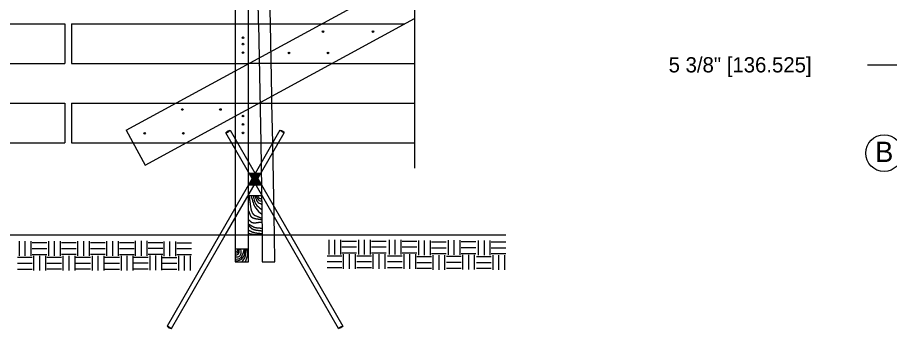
# Model space of a CAD drawing. Extents: x 49991 to 79985, y 47703 to 60542.
# Drawn here: x 50005.885 to 50009.323, y 49994.397 to 49995.622 of the extents above; entities that cross this region are included whole.
import ezdxf

# ---------------------------------------------------------------- set-up
doc = ezdxf.new("R2010")
doc.units = 0
for name, color, linetype in [('Level 1', 7, 'Continuous'), ('Level 2', 7, 'Continuous'), ('Level 3', 7, 'Continuous'), ('Level 4', 7, 'Continuous'), ('Level 6', 7, 'Continuous')]:
    doc.layers.add(name, color=color, linetype=linetype)

msp = doc.modelspace()

# ---------------------------------------------------------------- linework, layer by layer
at = {"layer": 'Level 1'}
for p, q in [((50006.3134, 49995.1775), (50007.4507, 49995.7955)), ((50006.7436, 49995.7523), (50006.7436, 49995.5963)), ((50006.7956, 49995.5963), (50006.7956, 49995.7523)), ((50006.8357, 49995.5963), (50006.8326, 49995.7523)), ((50006.8827, 49995.5963), (50006.8798, 49995.7523)), ((50005.0943, 49995.5963), (50006.0719, 49995.5963)), ((50006.0719, 49995.5963), (50006.0719, 49995.4403)), ((50006.0979, 49995.5963), (50006.0979, 49995.4403)), ((50006.0979, 49995.5963), (50007.0841, 49995.5963)), ((50006.388, 49995.0404), (50007.4507, 49995.618)), ((50005.3814, 49995.4403), (50006.0719, 49995.4403)), ((50006.0979, 49995.4403), (50006.797, 49995.4403)), ((50006.7436, 49995.4403), (50006.7436, 49995.4113)), ((50007.1237, 49995.4403), (50007.4507, 49995.4403)), ((50006.8885, 49995.2843), (50006.8879, 49995.3122)), ((50005.6684, 49995.2843), (50006.0719, 49995.2843)), ((50006.0719, 49995.2843), (50006.0719, 49995.1283)), ((50006.0979, 49995.2843), (50006.0979, 49995.1283)), ((50006.0979, 49995.2843), (50006.5099, 49995.2843)), ((50006.8367, 49995.2843), (50007.4507, 49995.2843)), ((50006.3134, 49995.1775), (50006.388, 49995.0404)), ((50006.7234, 49995.1776), (50006.8218, 49995.0072)), ((50006.9201, 49995.1775), (50006.8218, 49995.0072)), ((50006.8105, 49994.9876), (50006.7065, 49995.1678)), ((50006.833, 49994.9877), (50006.937, 49995.1678)), ((50005.7974, 49995.1283), (50006.0719, 49995.1283)), ((50006.0979, 49995.1283), (50006.3402, 49995.1283)), ((50006.5496, 49995.1283), (50007.4507, 49995.1283)), ((50006.7436, 49995.1283), (50006.7436, 49994.7643)), ((50006.7956, 49994.7643), (50006.7956, 49995.1283)), ((50006.845, 49995.1283), (50006.8495, 49994.7643)), ((50006.8985, 49994.7643), (50006.8914, 49995.1283)), ((50006.798, 49995.0092), (50006.8454, 49995.0092)), ((50006.7995, 49995.0066), (50006.8439, 49995.0066)), ((50006.801, 49995.004), (50006.8424, 49995.004)), ((50006.8025, 49995.0014), (50006.8409, 49995.0014)), ((50006.8105, 49994.9876), (50006.6815, 49994.7643)), ((50006.704, 49994.7643), (50006.8217, 49994.9682)), ((50006.7989, 49994.9676), (50006.8446, 49994.9676)), ((50006.8005, 49994.9702), (50006.8431, 49994.9702)), ((50006.802, 49994.9728), (50006.8416, 49994.9728)), ((50006.8035, 49994.9754), (50006.8401, 49994.9754)), ((50006.804, 49994.9988), (50006.8394, 49994.9988)), ((50006.805, 49994.978), (50006.8386, 49994.978)), ((50006.8055, 49994.9962), (50006.8379, 49994.9962)), ((50006.8065, 49994.9806), (50006.8371, 49994.9806)), ((50006.807, 49994.9936), (50006.8364, 49994.9936)), ((50006.808, 49994.9832), (50006.8356, 49994.9832)), ((50006.8085, 49994.991), (50006.8349, 49994.991)), ((50006.8095, 49994.9858), (50006.8341, 49994.9858)), ((50006.81, 49994.9884), (50006.8334, 49994.9884)), ((50006.9395, 49994.7643), (50006.8217, 49994.9682)), ((50006.833, 49994.9877), (50006.962, 49994.7643)), ((50006.7959, 49994.9624), (50006.8476, 49994.9624)), ((50006.7974, 49994.965), (50006.8461, 49994.965)), ((50006.8476, 49994.9194), (50006.7956, 49994.9194)), ((50006.7956, 49994.7643), (50006.7956, 49994.8423)), ((50007.8111, 49994.7643), (50000.0394, 49994.7643)), ((50005.8914, 49994.7409), (50005.8914, 49994.6831)), ((50005.9145, 49994.7409), (50005.9145, 49994.6831)), ((50005.9377, 49994.7409), (50005.9377, 49994.6831)), ((50005.943, 49994.7355), (50006.0009, 49994.7355)), ((50006.0073, 49994.7414), (50006.0073, 49994.6836)), ((50006.0304, 49994.7414), (50006.0304, 49994.6836)), ((50006.0535, 49994.7414), (50006.0535, 49994.6836)), ((50006.0589, 49994.736), (50006.1167, 49994.736)), ((50006.1219, 49994.7415), (50006.1219, 49994.6836)), ((50006.145, 49994.7415), (50006.145, 49994.6836)), ((50006.1681, 49994.7415), (50006.1681, 49994.6836)), ((50006.1735, 49994.7361), (50006.2313, 49994.7361)), ((50006.2362, 49994.7409), (50006.2362, 49994.6831)), ((50006.2593, 49994.7409), (50006.2593, 49994.6831)), ((50006.2824, 49994.7409), (50006.2824, 49994.6831)), ((50006.2878, 49994.7356), (50006.3456, 49994.7356)), ((50006.3494, 49994.742), (50006.3494, 49994.6841)), ((50006.3725, 49994.742), (50006.3725, 49994.6841)), ((50006.3956, 49994.742), (50006.3956, 49994.6841)), ((50006.401, 49994.7366), (50006.4588, 49994.7366)), ((50006.4621, 49994.7404), (50006.4621, 49994.6826)), ((50006.4852, 49994.7404), (50006.4852, 49994.6826)), ((50006.5084, 49994.7404), (50006.5084, 49994.6826)), ((50006.5137, 49994.735), (50006.5716, 49994.735)), ((50007.1124, 49994.747), (50007.1124, 49994.6892)), ((50007.1356, 49994.747), (50007.1356, 49994.6892)), ((50007.1587, 49994.747), (50007.1587, 49994.6892)), ((50007.164, 49994.7416), (50007.2219, 49994.7416)), ((50007.2294, 49994.747), (50007.2294, 49994.6892)), ((50007.2525, 49994.747), (50007.2525, 49994.6892)), ((50007.2756, 49994.747), (50007.2756, 49994.6892)), ((50007.281, 49994.7416), (50007.3388, 49994.7416)), ((50007.3504, 49994.747), (50007.3504, 49994.6892)), ((50007.3735, 49994.747), (50007.3735, 49994.6892)), ((50007.3967, 49994.747), (50007.3967, 49994.6892)), ((50007.402, 49994.7416), (50007.4599, 49994.7416)), ((50007.4658, 49994.7439), (50007.4658, 49994.686)), ((50007.4889, 49994.7439), (50007.4889, 49994.686)), ((50007.512, 49994.7439), (50007.512, 49994.686)), ((50007.5174, 49994.7385), (50007.5752, 49994.7385)), ((50007.5826, 49994.7449), (50007.5826, 49994.6871)), ((50007.6058, 49994.7449), (50007.6058, 49994.6871)), ((50007.6289, 49994.7449), (50007.6289, 49994.6871)), ((50007.6343, 49994.7395), (50007.6921, 49994.7395)), ((50007.7017, 49994.7439), (50007.7017, 49994.686)), ((50007.7248, 49994.7439), (50007.7248, 49994.686)), ((50007.7479, 49994.7439), (50007.7479, 49994.686)), ((50007.7533, 49994.7385), (50007.8111, 49994.7385)), ((50005.943, 49994.7124), (50006.0009, 49994.7124)), ((50006.0589, 49994.7129), (50006.1167, 49994.7129)), ((50006.1735, 49994.713), (50006.2313, 49994.713)), ((50006.2878, 49994.7124), (50006.3456, 49994.7124)), ((50006.401, 49994.7135), (50006.4588, 49994.7135)), ((50006.5137, 49994.7119), (50006.5716, 49994.7119)), ((50007.164, 49994.7185), (50007.2219, 49994.7185)), ((50007.164, 49994.6953), (50007.2219, 49994.6953)), ((50007.281, 49994.7185), (50007.3388, 49994.7185)), ((50007.281, 49994.6953), (50007.3388, 49994.6953)), ((50007.402, 49994.7185), (50007.4599, 49994.7185)), ((50007.402, 49994.6953), (50007.4599, 49994.6953)), ((50007.5174, 49994.7154), (50007.5752, 49994.7154)), ((50007.5174, 49994.6922), (50007.5752, 49994.6922)), ((50007.6343, 49994.7164), (50007.6921, 49994.7164)), ((50007.6343, 49994.6933), (50007.6921, 49994.6933)), ((50007.7533, 49994.7154), (50007.8111, 49994.7154)), ((50007.7533, 49994.6922), (50007.8111, 49994.6922)), ((50005.8852, 49994.6777), (50005.943, 49994.6777)), ((50005.943, 49994.6893), (50006.0009, 49994.6893)), ((50005.9488, 49994.6835), (50005.9488, 49994.6257)), ((50005.9719, 49994.6835), (50005.9719, 49994.6257)), ((50005.9951, 49994.6835), (50005.9951, 49994.6257)), ((50006.0011, 49994.6782), (50006.0589, 49994.6782)), ((50006.0589, 49994.6898), (50006.1167, 49994.6898)), ((50006.0647, 49994.684), (50006.0647, 49994.6262)), ((50006.0878, 49994.684), (50006.0878, 49994.6262)), ((50006.1109, 49994.684), (50006.1109, 49994.6262)), ((50006.1156, 49994.6782), (50006.1735, 49994.6782)), ((50006.1735, 49994.6898), (50006.2313, 49994.6898)), ((50006.1792, 49994.684), (50006.1792, 49994.6262)), ((50006.2024, 49994.684), (50006.2024, 49994.6262)), ((50006.2255, 49994.684), (50006.2255, 49994.6262)), ((50006.2299, 49994.6777), (50006.2878, 49994.6777)), ((50006.2878, 49994.6893), (50006.3456, 49994.6893)), ((50006.2935, 49994.6835), (50006.2935, 49994.6257)), ((50006.3167, 49994.6835), (50006.3167, 49994.6257)), ((50006.3398, 49994.6835), (50006.3398, 49994.6257)), ((50006.3432, 49994.6788), (50006.401, 49994.6788)), ((50006.401, 49994.6903), (50006.4588, 49994.6903)), ((50006.4068, 49994.6846), (50006.4068, 49994.6267)), ((50006.4299, 49994.6846), (50006.4299, 49994.6267)), ((50006.453, 49994.6846), (50006.453, 49994.6267)), ((50006.4559, 49994.6772), (50006.5137, 49994.6772)), ((50006.5137, 49994.6888), (50006.5716, 49994.6888)), ((50006.5195, 49994.683), (50006.5195, 49994.6252)), ((50006.5426, 49994.683), (50006.5426, 49994.6252)), ((50006.5658, 49994.683), (50006.5658, 49994.6252)), ((50007.1062, 49994.6838), (50007.164, 49994.6838)), ((50007.1062, 49994.6607), (50007.164, 49994.6607)), ((50007.1698, 49994.6896), (50007.1698, 49994.6317)), ((50007.193, 49994.6896), (50007.193, 49994.6317)), ((50007.2161, 49994.6896), (50007.2161, 49994.6317)), ((50007.2231, 49994.6838), (50007.281, 49994.6838)), ((50007.2231, 49994.6607), (50007.281, 49994.6607)), ((50007.2867, 49994.6896), (50007.2867, 49994.6317)), ((50007.3099, 49994.6896), (50007.3099, 49994.6317)), ((50007.333, 49994.6896), (50007.333, 49994.6317)), ((50007.3442, 49994.6838), (50007.402, 49994.6838)), ((50007.3442, 49994.6607), (50007.402, 49994.6607)), ((50007.4078, 49994.6896), (50007.4078, 49994.6317)), ((50007.4309, 49994.6896), (50007.4309, 49994.6317)), ((50007.4541, 49994.6896), (50007.4541, 49994.6317)), ((50007.4595, 49994.6807), (50007.5174, 49994.6807)), ((50007.4595, 49994.6575), (50007.5174, 49994.6575)), ((50007.5231, 49994.6865), (50007.5231, 49994.6286)), ((50007.5463, 49994.6865), (50007.5463, 49994.6286)), ((50007.5694, 49994.6865), (50007.5694, 49994.6286)), ((50007.5764, 49994.6817), (50007.6343, 49994.6817)), ((50007.5764, 49994.6586), (50007.6343, 49994.6586)), ((50007.64, 49994.6875), (50007.64, 49994.6297)), ((50007.6632, 49994.6875), (50007.6632, 49994.6297)), ((50007.6863, 49994.6875), (50007.6863, 49994.6297)), ((50007.6954, 49994.6807), (50007.7533, 49994.6807)), ((50007.6954, 49994.6575), (50007.7533, 49994.6575)), ((50007.759, 49994.6865), (50007.759, 49994.6286)), ((50007.7822, 49994.6865), (50007.7822, 49994.6286)), ((50007.8053, 49994.6865), (50007.8053, 49994.6286)), ((50005.8852, 49994.6546), (50005.943, 49994.6546)), ((50005.8852, 49994.6314), (50005.943, 49994.6314)), ((50006.0011, 49994.6551), (50006.0589, 49994.6551)), ((50006.0011, 49994.632), (50006.0589, 49994.632)), ((50006.1156, 49994.6551), (50006.1735, 49994.6551)), ((50006.1156, 49994.632), (50006.1735, 49994.632)), ((50006.2299, 49994.6546), (50006.2878, 49994.6546)), ((50006.2299, 49994.6315), (50006.2878, 49994.6315)), ((50006.3432, 49994.6557), (50006.401, 49994.6557)), ((50006.3432, 49994.6325), (50006.401, 49994.6325)), ((50006.4559, 49994.6541), (50006.5137, 49994.6541)), ((50006.4559, 49994.6309), (50006.5137, 49994.6309)), ((50007.1062, 49994.6375), (50007.164, 49994.6375)), ((50007.2231, 49994.6375), (50007.281, 49994.6375)), ((50007.3442, 49994.6375), (50007.402, 49994.6375)), ((50007.4595, 49994.6344), (50007.5174, 49994.6344)), ((50007.5764, 49994.6354), (50007.6343, 49994.6354)), ((50007.6954, 49994.6344), (50007.7533, 49994.6344))]:
    msp.add_line(p, q, dxfattribs=at)
for centre in [(50007.0896, 49995.5663), (50007.287, 49995.5663), (50006.7745, 49995.5416), (50006.7745, 49995.5166), (50006.7745, 49995.4833), (50006.9559, 49995.482), (50007.1095, 49995.482), (50006.5351, 49995.2594), (50006.6855, 49995.2594), (50006.7745, 49995.2338), (50006.7745, 49995.2005), (50006.3868, 49995.1657), (50006.5393, 49995.1657), (50006.7745, 49995.1673)]:
    msp.add_circle(centre, 0.00327, dxfattribs=at)
for points in [[(50006.7065, 49995.1678), (50006.7167, 49995.1715), (50006.7234, 49995.1776)], [(50006.7065, 49995.1678), (50006.716, 49995.1754), (50006.7234, 49995.1776)], [(50006.9201, 49995.1775), (50006.9317, 49995.1743), (50006.937, 49995.1678)], [(50006.9201, 49995.1775), (50006.9286, 49995.1729), (50006.937, 49995.1678)], [(50006.8068, 49994.9188), (50006.825, 49994.8711), (50006.8486, 49994.8469)], [(50006.8149, 49994.9194), (50006.825, 49994.8872), (50006.8472, 49994.867)], [(50006.8229, 49994.9181), (50006.831, 49994.8966), (50006.8479, 49994.8872)], [(50006.8263, 49994.9194), (50006.8385, 49994.9013), (50006.8472, 49994.898)], [(50006.8331, 49994.9188), (50006.8411, 49994.9094), (50006.8472, 49994.9107)], [(50006.796, 49994.7723), (50006.8162, 49994.7683), (50006.8472, 49994.7683)]]:
    msp.add_spline(points, degree=3, dxfattribs=at)
for points in [[(50006.7987, 49994.9188), (50006.7997, 49994.9111), (50006.8007, 49994.9033), (50006.8017, 49994.8956), (50006.8022, 49994.8917), (50006.8027, 49994.8879), (50006.8032, 49994.884), (50006.8037, 49994.8801), (50006.8042, 49994.8763), (50006.8047, 49994.8724), (50006.8048, 49994.8717), (50006.8049, 49994.8709), (50006.805, 49994.8702), (50006.8051, 49994.8695), (50006.8053, 49994.8687), (50006.8054, 49994.868), (50006.8058, 49994.8664), (50006.8062, 49994.8649), (50006.8066, 49994.8634), (50006.8074, 49994.8604), (50006.8086, 49994.8575), (50006.81, 49994.8546), (50006.8114, 49994.8519), (50006.8131, 49994.8494), (50006.8152, 49994.8472), (50006.8162, 49994.8461), (50006.8173, 49994.8451), (50006.8185, 49994.8443), (50006.8191, 49994.8439), (50006.8197, 49994.8435), (50006.8203, 49994.8431), (50006.821, 49994.8428), (50006.8216, 49994.8425), (50006.8223, 49994.8422), (50006.8265, 49994.8405), (50006.8307, 49994.8388), (50006.8349, 49994.8371), (50006.8392, 49994.8354), (50006.8434, 49994.8338), (50006.8476, 49994.8321)], [(50006.796, 49994.861), (50006.7966, 49994.8599), (50006.7971, 49994.8588), (50006.7975, 49994.8577), (50006.798, 49994.8565), (50006.7984, 49994.8554), (50006.7988, 49994.8542), (50006.7996, 49994.8518), (50006.8003, 49994.8494), (50006.8011, 49994.8471), (50006.8019, 49994.8448), (50006.803, 49994.8426), (50006.8042, 49994.8405), (50006.8049, 49994.8395), (50006.8056, 49994.8386), (50006.8065, 49994.8377), (50006.8069, 49994.8373), (50006.8074, 49994.8369), (50006.8079, 49994.8365), (50006.8081, 49994.8363), (50006.8083, 49994.8361), (50006.8086, 49994.8359), (50006.8087, 49994.8358), (50006.8089, 49994.8358), (50006.809, 49994.8357), (50006.8091, 49994.8356), (50006.8091, 49994.8356), (50006.8092, 49994.8355), (50006.8092, 49994.8355), (50006.8093, 49994.8355), (50006.8093, 49994.8355), (50006.8093, 49994.8354), (50006.8094, 49994.8354), (50006.8094, 49994.8354), (50006.8123, 49994.8336), (50006.8154, 49994.8322), (50006.8186, 49994.8312), (50006.8218, 49994.8302), (50006.8249, 49994.8295), (50006.8282, 49994.8291), (50006.8314, 49994.8287), (50006.8347, 49994.8283), (50006.8379, 49994.8278), (50006.8396, 49994.8276), (50006.8412, 49994.8274), (50006.8428, 49994.8271), (50006.8444, 49994.8269), (50006.846, 49994.8266), (50006.8476, 49994.8262)], [(50006.7953, 49994.8093), (50006.7963, 49994.8087), (50006.7974, 49994.8082), (50006.7984, 49994.8076), (50006.7994, 49994.807), (50006.8004, 49994.8063), (50006.8014, 49994.8057), (50006.8034, 49994.8045), (50006.8054, 49994.8032), (50006.8074, 49994.802), (50006.8095, 49994.8008), (50006.8115, 49994.7996), (50006.8136, 49994.7986), (50006.8147, 49994.798), (50006.8158, 49994.7975), (50006.8168, 49994.7971), (50006.8174, 49994.7968), (50006.8179, 49994.7966), (50006.8185, 49994.7964), (50006.8188, 49994.7963), (50006.8191, 49994.7962), (50006.8193, 49994.7961), (50006.8195, 49994.796), (50006.8196, 49994.796), (50006.8198, 49994.7959), (50006.8198, 49994.7959), (50006.8199, 49994.7959), (50006.82, 49994.7959), (50006.8201, 49994.7958), (50006.8201, 49994.7958), (50006.8202, 49994.7958), (50006.8224, 49994.7951), (50006.8247, 49994.7946), (50006.827, 49994.7942), (50006.8292, 49994.7938), (50006.8315, 49994.7936), (50006.8338, 49994.7935), (50006.8361, 49994.7933), (50006.8384, 49994.7932), (50006.8407, 49994.7931), (50006.8419, 49994.793), (50006.843, 49994.7929), (50006.8442, 49994.7929), (50006.8453, 49994.7928), (50006.8465, 49994.7927), (50006.8476, 49994.7925)], [(50006.796, 49994.8261), (50006.7967, 49994.8256), (50006.7973, 49994.8251), (50006.7979, 49994.8246), (50006.7985, 49994.824), (50006.7991, 49994.8235), (50006.7997, 49994.8229), (50006.8009, 49994.8218), (50006.8021, 49994.8206), (50006.8033, 49994.8195), (50006.8045, 49994.8184), (50006.8058, 49994.8174), (50006.8071, 49994.8165), (50006.8078, 49994.8161), (50006.8085, 49994.8157), (50006.8092, 49994.8154), (50006.8096, 49994.8152), (50006.81, 49994.8151), (50006.8103, 49994.8149), (50006.8105, 49994.8149), (50006.8107, 49994.8148), (50006.8109, 49994.8148), (50006.811, 49994.8147), (50006.8111, 49994.8147), (50006.8112, 49994.8147), (50006.8113, 49994.8147), (50006.8113, 49994.8146), (50006.8114, 49994.8146), (50006.8114, 49994.8146), (50006.8115, 49994.8146), (50006.8115, 49994.8146), (50006.8145, 49994.8139), (50006.8175, 49994.8136), (50006.8205, 49994.8136), (50006.8235, 49994.8136), (50006.8265, 49994.8138), (50006.8295, 49994.8143), (50006.8325, 49994.8147), (50006.8355, 49994.8151), (50006.8386, 49994.8156), (50006.8401, 49994.8158), (50006.8416, 49994.816), (50006.8431, 49994.8162), (50006.8446, 49994.8164), (50006.8461, 49994.8165), (50006.8476, 49994.8166)], [(50006.796, 49994.8039), (50006.7966, 49994.8033), (50006.7972, 49994.8027), (50006.7978, 49994.8021), (50006.7984, 49994.8014), (50006.799, 49994.8008), (50006.7996, 49994.8001), (50006.8008, 49994.7989), (50006.8019, 49994.7975), (50006.8031, 49994.7962), (50006.8042, 49994.795), (50006.8055, 49994.7938), (50006.8067, 49994.7926), (50006.8074, 49994.7921), (50006.808, 49994.7916), (50006.8087, 49994.7911), (50006.809, 49994.7909), (50006.8094, 49994.7906), (50006.8097, 49994.7904), (50006.8099, 49994.7903), (50006.8101, 49994.7902), (50006.8103, 49994.7901), (50006.8104, 49994.79), (50006.8104, 49994.79), (50006.8105, 49994.7899), (50006.8106, 49994.7899), (50006.8106, 49994.7899), (50006.8107, 49994.7899), (50006.8107, 49994.7898), (50006.8108, 49994.7898), (50006.8108, 49994.7898), (50006.8115, 49994.7894), (50006.8122, 49994.7891), (50006.8128, 49994.7888), (50006.8135, 49994.7885), (50006.8142, 49994.7882), (50006.8149, 49994.7879), (50006.8164, 49994.7874), (50006.8178, 49994.7869), (50006.8193, 49994.7865), (50006.8224, 49994.7858), (50006.8255, 49994.7851), (50006.8286, 49994.7847), (50006.8318, 49994.7842), (50006.835, 49994.7838), (50006.8381, 49994.7834), (50006.8397, 49994.7832), (50006.8413, 49994.783), (50006.8429, 49994.7827), (50006.8445, 49994.7825), (50006.846, 49994.7822), (50006.8476, 49994.7819)], [(50006.796, 49994.7851), (50006.7968, 49994.7847), (50006.7975, 49994.7844), (50006.7983, 49994.784), (50006.799, 49994.7836), (50006.7998, 49994.7832), (50006.8005, 49994.7828), (50006.802, 49994.782), (50006.8035, 49994.7812), (50006.805, 49994.7804), (50006.8065, 49994.7796), (50006.808, 49994.7789), (50006.8095, 49994.7782), (50006.8103, 49994.7778), (50006.8111, 49994.7775), (50006.8118, 49994.7772), (50006.8122, 49994.7771), (50006.8126, 49994.7769), (50006.813, 49994.7768), (50006.8132, 49994.7767), (50006.8134, 49994.7767), (50006.8136, 49994.7766), (50006.8137, 49994.7766), (50006.8138, 49994.7765), (50006.8139, 49994.7765), (50006.814, 49994.7765), (50006.8141, 49994.7764), (50006.8142, 49994.7764), (50006.8169, 49994.7756), (50006.8196, 49994.7749), (50006.8223, 49994.7744), (50006.8251, 49994.7739), (50006.8279, 49994.7735), (50006.8307, 49994.7732), (50006.8335, 49994.7728), (50006.8364, 49994.7725), (50006.8392, 49994.7722), (50006.8406, 49994.772), (50006.842, 49994.7719), (50006.8434, 49994.7717), (50006.8448, 49994.7716), (50006.8462, 49994.7714), (50006.8476, 49994.7712)]]:
    msp.add_open_spline(points, degree=3, dxfattribs=at)
at = {"layer": 'Level 2'}
msp.add_circle((50009.3018, 49995.0876), 0.072, dxfattribs=at)
at = {"layer": 'Level 3'}
msp.add_line((50009.236, 49995.4353), (50009.3697, 49995.4353), dxfattribs=at)
at = {"layer": 'Level 4'}
for p, q in [((50006.7436, 49995.5963), (50006.7436, 49995.4403)), ((50006.7956, 49995.1283), (50006.7956, 49995.5963)), ((50006.8357, 49995.5963), (50006.845, 49995.1283)), ((50006.8879, 49995.3122), (50006.8827, 49995.5963)), ((50007.0841, 49995.5963), (50007.4108, 49995.5963)), ((50007.1237, 49995.4403), (50006.797, 49995.4403)), ((50006.7436, 49995.4113), (50006.7436, 49995.1283)), ((50006.5099, 49995.2843), (50006.8367, 49995.2843)), ((50006.8914, 49995.1283), (50006.8885, 49995.2843)), ((50006.3402, 49995.1283), (50006.5496, 49995.1283)), ((50006.6815, 49994.7643), (50006.475, 49994.4066)), ((50006.4922, 49994.3974), (50006.704, 49994.7643)), ((50006.7436, 49994.7643), (50006.7436, 49994.7092)), ((50006.7956, 49994.7092), (50006.7956, 49994.7643)), ((50006.8495, 49994.7643), (50006.8495, 49994.6603)), ((50006.9005, 49994.6603), (50006.8985, 49994.7643)), ((50007.1513, 49994.3974), (50006.9395, 49994.7643)), ((50006.962, 49994.7643), (50007.1685, 49994.4067)), ((50006.8495, 49994.6603), (50006.9005, 49994.6603))]:
    msp.add_line(p, q, dxfattribs=at)
msp.add_lwpolyline([(50006.7436, 49994.6603), (50006.7956, 49994.6603), (50006.7956, 49994.7092), (50006.7436, 49994.7092)], close=True, dxfattribs=at)
for points in [[(50006.475, 49994.4066), (50006.4822, 49994.3996)], [(50006.4822, 49994.3996), (50006.4922, 49994.3974)], [(50007.1513, 49994.3974), (50007.1603, 49994.4009), (50007.1685, 49994.4067)], [(50007.1685, 49994.4067), (50007.159, 49994.4032), (50007.1513, 49994.3974)]]:
    msp.add_lwpolyline(points, dxfattribs=at)
for points in [[(50006.7433, 49994.6707), (50006.7601, 49994.6734), (50006.779, 49994.7083)], [(50006.744, 49994.7002), (50006.7527, 49994.7036), (50006.7541, 49994.7083)], [(50006.744, 49994.6949), (50006.7527, 49994.6969), (50006.7581, 49994.7083)], [(50006.744, 49994.6868), (50006.7547, 49994.6902), (50006.7601, 49994.7083)], [(50006.744, 49994.6794), (50006.7581, 49994.6808), (50006.7662, 49994.6895), (50006.7662, 49994.7083)], [(50006.744, 49994.6633), (50006.7655, 49994.6687), (50006.7797, 49994.6875), (50006.7831, 49994.7076)], [(50006.7709, 49994.6606), (50006.781, 49994.676), (50006.7878, 49994.7083)], [(50006.7831, 49994.6606), (50006.7898, 49994.676), (50006.7938, 49994.709)], [(50006.475, 49994.4066), (50006.4852, 49994.4034), (50006.4922, 49994.3974)]]:
    msp.add_spline(points, degree=3, dxfattribs=at)
at = {"layer": 'Level 6'}
msp.add_line((50007.4507, 49996.2335), (50007.4507, 49995.0283), dxfattribs=at)

# ---------------------------------------------------------------- texts
at = {"layer": 'Level 2'}
for s, height, p in [('5 3/8" [136.525]', 0.06, (50008.4523, 49995.4053)), ('B FRAME', 0.08, (50009.2668, 49995.0527))]:
    msp.add_text(s, height=height, dxfattribs=at).set_placement(p)

doc.saveas('drawing.dxf')
